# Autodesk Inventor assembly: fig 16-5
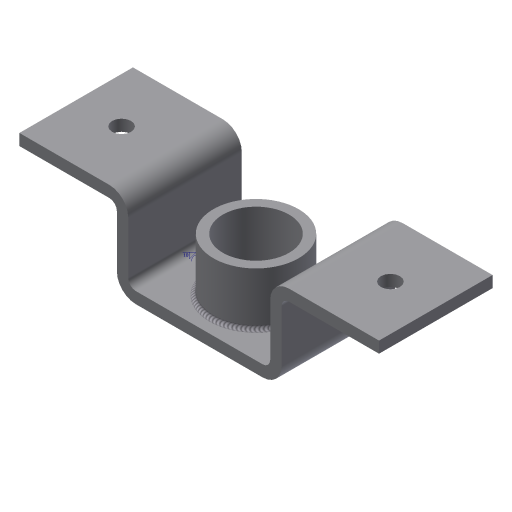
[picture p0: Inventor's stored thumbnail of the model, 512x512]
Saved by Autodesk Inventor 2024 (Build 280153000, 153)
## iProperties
Created: 2004-07
Part Number: fig 16-5
Document SubType Name: Weldment
Designer: CADCIM Technologies
Manufacturer: Standard
Standards Organization: Custom
Author: CADCIM Technologies
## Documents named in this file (3)
- D:\PROJECTS\Project 2023\RESOURCES INVENTOR 2024\RESOURCES INVENTOR 2024\Inventor_2023_Part\Inventor_2024_Part\c16_Inv_2024_prt\fig 16-5\fig 16-5.iam
- D:\PROJECTS\Project 2023\RESOURCES INVENTOR 2024\RESOURCES INVENTOR 2024\Inventor_2023_Part\Inventor_2024_Part\c16_Inv_2024_prt\fig 16-5\Bracket.ipt
- D:\PROJECTS\Project 2023\RESOURCES INVENTOR 2024\RESOURCES INVENTOR 2024\Inventor_2023_Part\Inventor_2024_Part\c16_Inv_2024_prt\fig 16-5\cylinder.ipt
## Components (2 placed, 2 different names)
1. Bracket:1 — Insert:1
2. cylinder:1 — Insert:1
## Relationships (1: Insert 1)
- Insert:1: Bracket:1 ↔ cylinder:1
